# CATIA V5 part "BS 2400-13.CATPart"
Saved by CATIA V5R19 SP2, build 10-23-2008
Part number: BS 2400-13
Bounding box of the stored display mesh (mm): x -37.351 to 37.351, y -37.351 to 37.351, z 0 to 71
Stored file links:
  C:\Users\Bora\Desktop\3D Katı model\BS serisi\BS 2400\BS 2400-13.CATPart
  C:\Program Files\Dassault Systemes\B19\intel_a\reffiles\standard\MetricThickPitch.txt
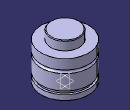
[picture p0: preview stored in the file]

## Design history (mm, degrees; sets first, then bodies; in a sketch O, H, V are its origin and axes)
Body1 (main body)
  Sketch1 on yz-plane, origin (0, 0, 0), H (0, 1, 0), V (0, 0, 1)
    point P1 (22.5, 70)
    point P3 (22.5, 70)
    point P7 (37.5, 41.5)
    point P9 (37.5, 41.5)
    point P10 (37.5, 36.5)
    point P14 (37.5, 36.5)
    line L1 (22.5, 70) -> (22.5, 57)
    arc A1 centre (21.5, 70) radius 1 from (22.5, 70) to (21.5, 71) ccw
    line L2 (37.5, 0) -> (37.5, 8)
    line L3 (37.5, 41.5) -> (37.5, 57)
    arc A2 centre (37.5, 39) radius 2.5 from (37.5, 41.5) to (37.5, 36.5) ccw
    line L4 (34.5, 13) -> (34.5, 8)
    line L5 (37.5, 13) -> (37.5, 36.5)
    line L6 (21.5, 71) -> (0, 71)
    point P15 (0, 71)
    line L7 (22.5, 57) -> (37.5, 57)
    line L8 (0, 0) -> (37.5, 0)
    line L9 (34.5, 13) -> (37.5, 13)
    line L10 (34.5, 8) -> (37.5, 8)
    coincidence: P15 V, P1 P3, P7 P9, P10 P14
    tangency: L6 A1
    horizontal: L7 H, L8 H, L9 H, L10 H
  Shaft1: profile Sketch1, axis Sketch1.V, angle 360
  Sketch2 on face of Shaft1 from Sketch1.L8, origin (0, 0, 0), H (1, 0, 0), V (0, -1, 0)
    point P1 (20, 0)
    distance P1 V = 20
  Hole1: placed by Sketch2, at (20, 0, 0) direction (0, 0, 1), diameter 6.647, depth 5, threaded "M8", thread diameter 8, thread depth 5, pitch 1.25
  CircPattern1: of Hole1, instances 4, angular step 90, axis from xy-plane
